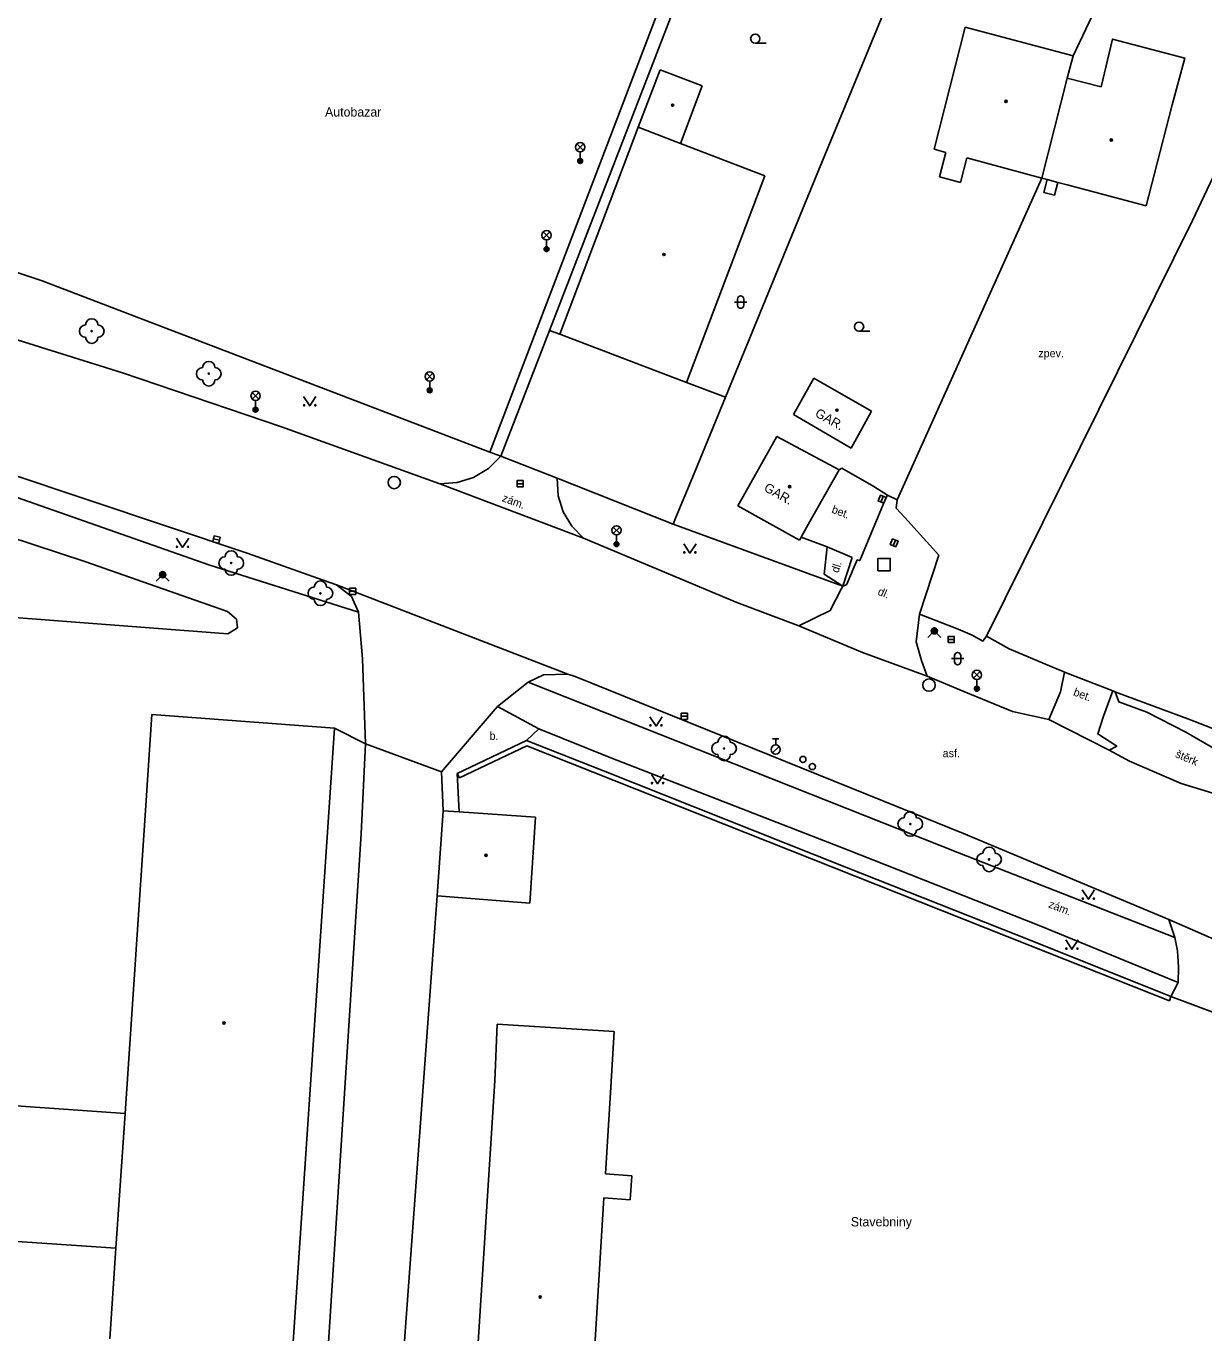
# Model space of a CAD drawing. Extents: x -598233 to -596890, y -1157848 to -1156431.
# Drawn here: x -597364.6 to -597268.9, y -1157742 to -1157635.8 of the extents above; entities that cross this region are included whole.
import ezdxf

# ---------------------------------------------------------------- set-up
doc = ezdxf.new("R2010")
doc.units = 0
for name, color, linetype in [('Level 10', 7, 'Continuous'), ('Level 11', 7, 'Continuous'), ('Level 22', 7, 'Continuous'), ('Level 26', 7, 'Continuous'), ('Level 27', 7, 'Continuous'), ('Level 28', 7, 'Continuous'), ('Level 31', 7, 'Continuous'), ('Level 33', 7, 'Continuous'), ('Level 36', 7, 'Continuous'), ('Level 39', 7, 'Continuous'), ('Level 40', 7, 'Continuous'), ('Level 41', 7, 'Continuous'), ('Level 42', 7, 'Continuous'), ('Level 5', 7, 'Continuous'), ('Level 51', 7, 'Continuous'), ('Level 7', 7, 'Continuous'), ('Level 8', 7, 'Continuous')]:
    doc.layers.add(name, color=color, linetype=linetype)

msp = doc.modelspace()

# ---------------------------------------------------------------- linework, layer by layer
at = {"layer": 'Level 10'}
for points in [[(-597382.9699, -1157656.14), (-597381.3, -1157656.62), (-597376.66, -1157657.97), (-597369.85, -1157659.94), (-597364.81, -1157661.47), (-597356.76, -1157664), (-597343.86, -1157668.37), (-597331.01, -1157673)], [(-597339.38, -1157681.22), (-597340.4696, -1157680.8289), (-597346.65, -1157678.64), (-597366.125, -1157672.11)], [(-597331.01, -1157673), (-597319.33, -1157677.42)], [(-597319.33, -1157677.42), (-597306.88, -1157682.64)], [(-597337.61, -1157683.43), (-597337.27, -1157687.21)], [(-597306.88, -1157682.64), (-597301.84, -1157684.53)], [(-597296.68, -1157686.72), (-597301.84, -1157684.53)], [(-597337.27, -1157687.21), (-597337.03, -1157694.12)], [(-597291.41, -1157688.64), (-597296.68, -1157686.72)], [(-597323.81, -1157689.12), (-597322.59, -1157688.52), (-597320.6, -1157688.47)], [(-597295.02, -1157698.76), (-597320.01, -1157688.6599), (-597320.6, -1157688.47)], [(-597288.44, -1157689.88), (-597291.41, -1157688.64)], [(-597326.32, -1157691.1), (-597323.81, -1157689.12)], [(-597288.44, -1157689.88), (-597284.49, -1157691.5)], [(-597330.87, -1157696.39), (-597326.5, -1157691.31), (-597326.32, -1157691.1)], [(-597281.53, -1157692.16), (-597284.49, -1157691.5)], [(-597276.64, -1157694.64), (-597281.53, -1157692.16)], [(-597275, -1157695.53), (-597276.64, -1157694.64)], [(-597270.8, -1157697.34), (-597275, -1157695.53)], [(-597266.62, -1157698.61), (-597270.8, -1157697.34)], [(-597295.02, -1157698.76), (-597288.48, -1157701.4099), (-597271.78, -1157708.38)], [(-597271.78, -1157708.38), (-597271.31, -1157709.84)], [(-597271.31, -1157709.84), (-597271.1, -1157710.94), (-597271, -1157712.26), (-597271.03, -1157713.5)], [(-597271.03, -1157713.5), (-597271.63, -1157714.64)]]:
    msp.add_lwpolyline(points, dxfattribs=at)
at = {"layer": 'Level 11'}
for points in [[(-597279.56, -1157638.27), (-597275.18, -1157629)], [(-597271.53, -1157642.24), (-597270.49, -1157638.44), (-597276.36, -1157636.89), (-597277.28, -1157640.77)], [(-597281.95, -1157649.36), (-597281.67, -1157648.3)], [(-597281.08, -1157649.58), (-597281.95, -1157649.36)], [(-597280.8, -1157648.53), (-597281.08, -1157649.58)], [(-597321.26, -1157660.87), (-597322.09, -1157660.56)], [(-597310.96, -1157664.78), (-597307.81, -1157665.97)], [(-597326.04, -1157670.77), (-597327.04, -1157671.76), (-597328.25, -1157672.49), (-597329.6, -1157672.9099), (-597331.01, -1157673)], [(-597319.33, -1157677.42), (-597320.28, -1157676.45), (-597320.9699, -1157675.29), (-597321.38, -1157673.99), (-597321.47, -1157672.56)], [(-597368.98, -1157672.85), (-597349.77, -1157679.58), (-597337.61, -1157683.43), (-597338.18, -1157682.16), (-597339.38, -1157681.22)], [(-597297.1, -1157679.17), (-597296.9, -1157679.25), (-597294.77, -1157674.17), (-597294.64, -1157673.94)], [(-597297.52, -1157679), (-597299.54, -1157678.14)], [(-597298.28, -1157681.32), (-597297.52, -1157679)], [(-597297.98, -1157681.22), (-597297.1, -1157679.17)], [(-597320.6, -1157688.47), (-597339.38, -1157681.22)], [(-597301.84, -1157684.53), (-597299.29, -1157683.3), (-597298.41, -1157681.56), (-597298.28, -1157681.32)], [(-597298.28, -1157681.32), (-597297.98, -1157681.22)], [(-597291.41, -1157688.64), (-597291.89, -1157687.36), (-597292.3, -1157685.84), (-597292.04, -1157683.6)], [(-597280.26, -1157688.3), (-597280.58, -1157689.89), (-597281.53, -1157692.16)], [(-597323.81, -1157689.12), (-597288.78, -1157702.99), (-597271.31, -1157709.84)], [(-597276.34, -1157689.83), (-597277.11, -1157691.88), (-597277.57, -1157693.32), (-597276.02, -1157694.31), (-597276.64, -1157694.64)], [(-597264.32, -1157694.38), (-597265.14, -1157694.86), (-597265.95, -1157695.13), (-597267.33, -1157694.96), (-597270.4, -1157693.19), (-597273.59, -1157691.54), (-597275.85, -1157690.72), (-597276.15, -1157689.91)], [(-597322.97, -1157692.91), (-597326.32, -1157691.1)], [(-597323.95, -1157693.84), (-597322.97, -1157692.91), (-597317.11, -1157695.26)], [(-597297.9, -1157702.72), (-597317.11, -1157695.26)], [(-597329.58, -1157696.52), (-597329.43, -1157699.65)], [(-597297.9, -1157702.72), (-597282.31, -1157708.88), (-597271.03, -1157713.5)], [(-597271.78, -1157708.38), (-597261.78, -1157712.78)], [(-597356.56, -1157724.13), (-597386.18, -1157722.07), (-597386.94, -1157733.07), (-597357.3, -1157735.09)]]:
    msp.add_lwpolyline(points, dxfattribs=at)
at = {"layer": 'Level 22'}
for centre in [(-597359.27, -1157660.61), (-597349.76, -1157664.07), (-597347.94, -1157679.44), (-597340.7, -1157681.9), (-597307.91, -1157694.5), (-597292.79, -1157700.63), (-597286.39, -1157703.51)]:
    msp.add_circle(centre, 0.05, dxfattribs=at)
for centre, start, end in [((-597359.27, -1157660.11), 0, 180), ((-597359.77, -1157660.61), 90, 270), ((-597359.27, -1157661.11), 180, 0), ((-597358.77, -1157660.61), 270, 90), ((-597349.76, -1157663.57), 0, 180), ((-597350.26, -1157664.07), 90, 270), ((-597349.26, -1157664.07), 270, 90), ((-597349.76, -1157664.57), 180, 0), ((-597348.44, -1157679.44), 90, 270), ((-597347.94, -1157678.94), 0, 180), ((-597347.44, -1157679.44), 270, 90), ((-597347.94, -1157679.94), 180, 0), ((-597340.7, -1157681.4), 0, 180), ((-597341.2, -1157681.9), 90, 270), ((-597340.2, -1157681.9), 270, 90), ((-597340.7, -1157682.4), 180, 0), ((-597308.41, -1157694.5), 90, 270), ((-597307.91, -1157694), 0, 180), ((-597307.41, -1157694.5), 270, 90), ((-597307.91, -1157695), 180, 0), ((-597293.29, -1157700.63), 90, 270), ((-597292.79, -1157700.13), 0, 180), ((-597292.29, -1157700.63), 270, 90), ((-597292.79, -1157701.13), 180, 0), ((-597286.39, -1157703.01), 0, 180), ((-597286.89, -1157703.51), 90, 270), ((-597285.89, -1157703.51), 270, 90), ((-597286.39, -1157704.01), 180, 0)]:
    msp.add_arc(centre, 0.5, start, end, dxfattribs=at)
at = {"layer": 'Level 26'}
msp.add_lwpolyline([(-597295.42, -1157680.07), (-597294.42, -1157680.07), (-597294.42, -1157679.07), (-597295.42, -1157679.07)], close=True, dxfattribs=at)
at = {"layer": 'Level 27'}
for p, q in [((-597324.72, -1157673), (-597324.22, -1157673)), ((-597295.1767, -1157674.4906), (-597294.9833, -1157674.0294)), ((-597349.3832, -1157677.4821), (-597348.8968, -1157677.5979)), ((-597294.1867, -1157678.0406), (-597293.9933, -1157677.5794)), ((-597338.32, -1157681.74), (-597337.82, -1157681.74)), ((-597289.72, -1157685.65), (-597289.22, -1157685.65)), ((-597311.39, -1157691.89), (-597310.89, -1157691.89))]:
    msp.add_line(p, q, dxfattribs=at)
for points in [[(-597324.72, -1157673.25), (-597324.22, -1157673.25), (-597324.22, -1157672.75), (-597324.72, -1157672.75)], [(-597294.9461, -1157674.5872), (-597294.7528, -1157674.1261), (-597295.2139, -1157673.9328), (-597295.4072, -1157674.3939)], [(-597349.4411, -1157677.7253), (-597348.9547, -1157677.8411), (-597348.8389, -1157677.3547), (-597349.3253, -1157677.2389)], [(-597293.9561, -1157678.1372), (-597293.7628, -1157677.6761), (-597294.2239, -1157677.4828), (-597294.4172, -1157677.9439)], [(-597338.32, -1157681.99), (-597337.82, -1157681.99), (-597337.82, -1157681.49), (-597338.32, -1157681.49)], [(-597289.72, -1157685.9), (-597289.22, -1157685.9), (-597289.22, -1157685.4), (-597289.72, -1157685.4)], [(-597311.39, -1157692.14), (-597310.89, -1157692.14), (-597310.89, -1157691.64), (-597311.39, -1157691.64)]]:
    msp.add_lwpolyline(points, close=True, dxfattribs=at)
for centre in [(-597334.7, -1157672.9099), (-597291.27, -1157689.35)]:
    msp.add_circle(centre, 0.5, dxfattribs=at)
at = {"layer": 'Level 28'}
for p, q in [((-597303.9699, -1157693.715), (-597303.4699, -1157693.715)), ((-597303.7199, -1157694.215), (-597303.7199, -1157693.715)), ((-597303.9779, -1157694.862), (-597303.4479, -1157694.332))]:
    msp.add_line(p, q, dxfattribs=at)
for centre, radius in [((-597303.7199, -1157694.59), 0.375), ((-597301.51, -1157695.39), 0.25), ((-597300.74, -1157695.9699), 0.25)]:
    msp.add_circle(centre, radius, dxfattribs=at)
at = {"layer": 'Level 31'}
for points in [[(-597354.04, -1157680.92), (-597353.51, -1157680.39), (-597352.98, -1157680.92)], [(-597291.37, -1157685.48), (-597290.84, -1157684.95), (-597290.31, -1157685.48)]]:
    msp.add_lwpolyline(points, dxfattribs=at)
for centre, radius in [((-597353.51, -1157680.39), 0.25), ((-597353.51, -1157680.39), 0.18), ((-597353.51, -1157680.39), 0.11), ((-597290.84, -1157684.95), 0.25), ((-597290.84, -1157684.95), 0.18), ((-597290.84, -1157684.95), 0.11)]:
    msp.add_circle(centre, radius, dxfattribs=at)
at = {"layer": 'Level 33'}
for p, q in [((-597319.865, -1157645.94), (-597319.335, -1157645.41)), ((-597319.865, -1157645.41), (-597319.335, -1157645.94)), ((-597319.6, -1157646.05), (-597319.6, -1157646.8)), ((-597322.595, -1157653.09), (-597322.065, -1157652.56)), ((-597322.595, -1157652.56), (-597322.065, -1157653.09)), ((-597322.33, -1157653.2), (-597322.33, -1157653.95)), ((-597332.085, -1157664.56), (-597331.555, -1157664.03)), ((-597332.085, -1157664.03), (-597331.555, -1157664.56)), ((-597331.82, -1157664.67), (-597331.82, -1157665.42)), ((-597346.225, -1157666.13), (-597345.695, -1157665.6)), ((-597346.225, -1157665.6), (-597345.695, -1157666.13)), ((-597345.96, -1157666.24), (-597345.96, -1157666.99)), ((-597316.915, -1157677.0499), (-597316.385, -1157676.5199)), ((-597316.915, -1157676.5199), (-597316.385, -1157677.0499)), ((-597316.65, -1157677.1599), (-597316.65, -1157677.9099)), ((-597287.645, -1157688.79), (-597287.115, -1157688.26)), ((-597287.645, -1157688.26), (-597287.115, -1157688.79)), ((-597287.38, -1157688.9), (-597287.38, -1157689.65))]:
    msp.add_line(p, q, dxfattribs=at)
for centre, radius in [((-597319.6, -1157645.675), 0.375), ((-597319.6, -1157646.8), 0.2), ((-597319.6, -1157646.8), 0.1445), ((-597319.6, -1157646.8), 0.0876), ((-597322.33, -1157652.825), 0.375), ((-597322.33, -1157653.95), 0.2), ((-597322.33, -1157653.95), 0.1445), ((-597322.33, -1157653.95), 0.0876), ((-597331.82, -1157664.295), 0.375), ((-597331.82, -1157665.42), 0.2), ((-597331.82, -1157665.42), 0.1445), ((-597331.82, -1157665.42), 0.0876), ((-597345.96, -1157665.865), 0.375), ((-597345.96, -1157666.99), 0.2), ((-597345.96, -1157666.99), 0.1445), ((-597345.96, -1157666.99), 0.0876), ((-597316.65, -1157676.7849), 0.375), ((-597316.65, -1157677.9099), 0.2), ((-597316.65, -1157677.9099), 0.1445), ((-597316.65, -1157677.9099), 0.0876), ((-597287.38, -1157688.525), 0.375), ((-597287.38, -1157689.65), 0.2), ((-597287.38, -1157689.65), 0.1445), ((-597287.38, -1157689.65), 0.0876)]:
    msp.add_circle(centre, radius, dxfattribs=at)
at = {"layer": 'Level 36'}
for p, q in [((-597305.38, -1157637.235), (-597304.505, -1157637.235)), ((-597307.066, -1157658.256), (-597306.066, -1157658.256)), ((-597306.816, -1157658.006), (-597306.816, -1157658.506)), ((-597306.316, -1157658.006), (-597306.316, -1157658.506)), ((-597296.95, -1157660.625), (-597296.075, -1157660.625)), ((-597289.446, -1157687.206), (-597288.446, -1157687.206)), ((-597289.196, -1157686.956), (-597289.196, -1157687.456)), ((-597288.696, -1157686.956), (-597288.696, -1157687.456))]:
    msp.add_line(p, q, dxfattribs=at)
for points in [[(-597342.06, -1157665.93), (-597341.56, -1157666.68), (-597341.06, -1157665.93)], [(-597352.39, -1157677.43), (-597351.89, -1157678.18), (-597351.39, -1157677.43)], [(-597311.19, -1157677.88), (-597310.69, -1157678.63), (-597310.19, -1157677.88)], [(-597313.94, -1157691.93), (-597313.44, -1157692.68), (-597312.94, -1157691.93)], [(-597313.81, -1157696.61), (-597313.31, -1157697.36), (-597312.81, -1157696.61)], [(-597278.83, -1157705.99), (-597278.33, -1157706.74), (-597277.83, -1157705.99)], [(-597280.1599, -1157710.05), (-597279.6599, -1157710.8), (-597279.1599, -1157710.05)]]:
    msp.add_lwpolyline(points, dxfattribs=at)
for centre, radius in [((-597305.3801, -1157636.8599), 0.375), ((-597296.9501, -1157660.2499), 0.375), ((-597342.0102, -1157666.6298), 0.05), ((-597341.1108, -1157666.6298), 0.05), ((-597352.3402, -1157678.1298), 0.05), ((-597351.4408, -1157678.1298), 0.05), ((-597311.1402, -1157678.5798), 0.05), ((-597310.2408, -1157678.5798), 0.05), ((-597313.8902, -1157692.6298), 0.05), ((-597312.9908, -1157692.6298), 0.05), ((-597313.7602, -1157697.3098), 0.05), ((-597312.8608, -1157697.3098), 0.05), ((-597278.7802, -1157706.6898), 0.05), ((-597277.8808, -1157706.6898), 0.05), ((-597280.1101, -1157710.7498), 0.05), ((-597279.2107, -1157710.7498), 0.05)]:
    msp.add_circle(centre, radius, dxfattribs=at)
for centre, start, end in [((-597306.5657, -1157658.0063), 0, 180), ((-597306.5657, -1157658.5063), 180, 0), ((-597288.9457, -1157686.9563), 0, 180), ((-597288.9457, -1157687.4563), 180, 0)]:
    msp.add_arc(centre, 0.25, start, end, dxfattribs=at)
at = {"layer": 'Level 39'}
for centre, radius in [((-597285.01, -1157641.96), 0.09), ((-597285.01, -1157641.96), 0.0398), ((-597312.09, -1157642.26), 0.09), ((-597312.09, -1157642.26), 0.0398), ((-597276.4699, -1157645.09), 0.09), ((-597276.4699, -1157645.09), 0.0398), ((-597312.8, -1157654.39), 0.09), ((-597312.8, -1157654.39), 0.0398), ((-597298.75, -1157667.03), 0.09), ((-597298.75, -1157667.03), 0.0398), ((-597302.59, -1157673.24), 0.09), ((-597302.59, -1157673.24), 0.0398), ((-597327.25, -1157703.18), 0.09), ((-597327.25, -1157703.18), 0.0398), ((-597348.53, -1157716.8), 0.09), ((-597348.53, -1157716.8), 0.0398), ((-597322.85, -1157739.05), 0.09), ((-597322.85, -1157739.05), 0.0398)]:
    msp.add_circle(centre, radius, dxfattribs=at)
at = {"layer": 'Level 5'}
for points in [[(-597290.84, -1157645.84), (-597288.32, -1157635.92)], [(-597288.32, -1157635.92), (-597279.56, -1157638.27)], [(-597279.56, -1157638.27), (-597280.04, -1157640.07)], [(-597314.89, -1157644.06), (-597313.1, -1157639.39)], [(-597313.1, -1157639.39), (-597309.68, -1157640.7)], [(-597309.68, -1157640.7), (-597311.46, -1157645.38)], [(-597280.04, -1157640.07), (-597282.11, -1157648.18)], [(-597280.04, -1157640.07), (-597277.28, -1157640.77)], [(-597271.53, -1157642.24), (-597272.5, -1157646.02)], [(-597321.26, -1157660.87), (-597314.89, -1157644.06)], [(-597314.89, -1157644.06), (-597311.46, -1157645.38)], [(-597311.46, -1157645.38), (-597304.59, -1157647.99)], [(-597289.89, -1157646.1), (-597290.84, -1157645.84)], [(-597290.42, -1157648.08), (-597289.89, -1157646.1)], [(-597272.5, -1157646.02), (-597273.64, -1157650.45)], [(-597288.19, -1157646.55), (-597288.7199, -1157648.54)], [(-597282.11, -1157648.18), (-597288.19, -1157646.55)], [(-597304.59, -1157647.99), (-597310.96, -1157664.78)], [(-597288.7199, -1157648.54), (-597290.42, -1157648.08)], [(-597281.67, -1157648.3), (-597282.11, -1157648.18)], [(-597280.8, -1157648.53), (-597281.67, -1157648.3)], [(-597280.06, -1157648.7199), (-597280.8, -1157648.53)], [(-597273.64, -1157650.45), (-597280.06, -1157648.7199)], [(-597310.96, -1157664.78), (-597321.26, -1157660.87)], [(-597302.27, -1157667.37), (-597300.63, -1157664.44)], [(-597300.63, -1157664.44), (-597295.93, -1157667.11)], [(-597297.59, -1157670.11), (-597302.27, -1157667.37)], [(-597295.93, -1157667.11), (-597297.59, -1157670.11)], [(-597306.37, -1157674.04), (-597303.64, -1157669.17)], [(-597303.64, -1157669.17), (-597298.57, -1157671.87)], [(-597298.57, -1157671.87), (-597300.94, -1157676.08)], [(-597306.8, -1157674.81), (-597306.37, -1157674.04)], [(-597301.79, -1157677.58), (-597306.8, -1157674.81)], [(-597300.94, -1157676.08), (-597301.66, -1157677.35), (-597301.79, -1157677.58)], [(-597354.88, -1157699.13), (-597354.38, -1157691.74)], [(-597354.38, -1157691.74), (-597339.56, -1157692.85)], [(-597342.9699, -1157743.49), (-597339.56, -1157692.85)], [(-597354.88, -1157699.13), (-597356.56, -1157724.13), (-597357.3, -1157735.09), (-597357.79, -1157742.43)], [(-597331.2, -1157706.4699), (-597330.7199, -1157699.56)], [(-597330.7199, -1157699.56), (-597329.43, -1157699.65), (-597323.23, -1157700.07)], [(-597323.23, -1157700.07), (-597323.68, -1157707.06)], [(-597323.68, -1157707.06), (-597331.2, -1157706.4699)], [(-597326.52, -1157721.49), (-597326.34, -1157716.9)], [(-597326.34, -1157716.9), (-597316.84, -1157717.48)], [(-597316.84, -1157717.48), (-597317.12, -1157722)], [(-597328.85, -1157758), (-597326.52, -1157721.49)], [(-597317.55, -1157729.04), (-597317.12, -1157722)], [(-597315.4, -1157729.2), (-597317.55, -1157729.04)], [(-597315.54, -1157731.14), (-597315.4, -1157729.2)], [(-597317.67, -1157730.98), (-597319.36, -1157758.55)], [(-597317.67, -1157730.98), (-597315.54, -1157731.14)]]:
    msp.add_lwpolyline(points, dxfattribs=at)
at = {"layer": 'Level 51'}
for points in [[(-597370.39, -1157675.84), (-597359.84, -1157679.31)], [(-597359.84, -1157679.31), (-597348.25, -1157683.38)], [(-597348.25, -1157683.38), (-597347.52, -1157684.01)], [(-597367.67, -1157683.71), (-597348.2199, -1157685.18)], [(-597347.52, -1157684.01), (-597347.44, -1157684.71)], [(-597348.2199, -1157685.18), (-597347.44, -1157684.71)], [(-597337.38, -1157701.44), (-597337.03, -1157694.12)], [(-597330.87, -1157696.39), (-597330.7199, -1157699.56)], [(-597340.37, -1157747.81), (-597337.38, -1157701.44)], [(-597333.99, -1157744.43), (-597331.2, -1157706.4699)]]:
    msp.add_lwpolyline(points, dxfattribs=at)
at = {"layer": 'Level 7'}
for points in [[(-597326.04, -1157670.77), (-597322.09, -1157660.56), (-597304.52, -1157615.14)], [(-597306.09, -1157615.82), (-597326.93, -1157670.43)], [(-597312.06, -1157676.28), (-597311.87, -1157675.8), (-597310.49, -1157672.49), (-597307.81, -1157665.97), (-597300.24, -1157647.57), (-597292.3, -1157628.34)], [(-597262.75, -1157636.58), (-597269.87, -1157651.62), (-597286.6, -1157685.39)], [(-597282.11, -1157648.18), (-597284.23, -1157652.9)], [(-597363.3, -1157656.54), (-597375.03, -1157652.6), (-597381.15, -1157650.54)], [(-597284.23, -1157652.9), (-597293.86, -1157674.3)], [(-597326.93, -1157670.43), (-597363.3, -1157656.54)], [(-597326.04, -1157670.77), (-597326.93, -1157670.43)], [(-597298.57, -1157671.87), (-597298.34, -1157671.75)], [(-597321.47, -1157672.56), (-597312.06, -1157676.28)], [(-597295.76, -1157673.22), (-597294.64, -1157673.94)], [(-597293.86, -1157674.3), (-597293.94, -1157675)], [(-597312.06, -1157676.28), (-597298.28, -1157681.32)], [(-597301.66, -1157677.35), (-597299.54, -1157678.14), (-597299.79, -1157680.36)], [(-597290.48, -1157678.8), (-597292.04, -1157683.6)], [(-597298.28, -1157681.32), (-597299.79, -1157680.36)], [(-597292.04, -1157683.6), (-597288.9, -1157684.82)], [(-597288.9, -1157684.82), (-597287.76, -1157685.31)], [(-597287.76, -1157685.31), (-597286.89, -1157685.78), (-597286.6, -1157685.39), (-597284.75, -1157686.42), (-597280.78, -1157688.09)], [(-597339.56, -1157692.85), (-597337.03, -1157694.12)], [(-597270.26, -1157692.09), (-597264.89, -1157694.18)], [(-597329.58, -1157696.52), (-597323.95, -1157693.84), (-597317.7, -1157696.32), (-597297.97, -1157704.17), (-597282.93, -1157710.13), (-597271.63, -1157714.64)], [(-597329.4, -1157696.89), (-597323.93, -1157694.28), (-597283.08, -1157710.5), (-597271.75, -1157714.98)], [(-597329.58, -1157696.52), (-597329.4, -1157696.89)], [(-597271.75, -1157714.98), (-597271.63, -1157714.64)]]:
    msp.add_lwpolyline(points, dxfattribs=at)
at = {"layer": 'Level 8'}
for points in [[(-597326.04, -1157670.77), (-597321.47, -1157672.56)], [(-597298.34, -1157671.75), (-597295.76, -1157673.22)], [(-597293.86, -1157674.3), (-597294.64, -1157673.94)], [(-597293.94, -1157675), (-597293.23, -1157675.74), (-597290.48, -1157678.8)], [(-597275.89, -1157690.01), (-597276.15, -1157689.91), (-597276.34, -1157689.83), (-597280.26, -1157688.3), (-597280.42, -1157688.23), (-597280.78, -1157688.09)], [(-597275.89, -1157690.01), (-597270.26, -1157692.09)], [(-597330.87, -1157696.39), (-597337.03, -1157694.12)], [(-597265.96, -1157716.76), (-597271.63, -1157714.64)]]:
    msp.add_lwpolyline(points, dxfattribs=at)

# ---------------------------------------------------------------- texts
at = {"layer": 'Level 40'}
for s, p in [('zpev.', (-597282.39, -1157662.73)), ('b.', (-597326.96, -1157693.8)), ('asf.', (-597290.16, -1157695.21))]:
    msp.add_text(s, height=0.65, dxfattribs=at).set_placement(p)
for s, rotation, p in [('zám.', 339.837396, (-597325.99, -1157674.41)), ('bet.', 339.502659, (-597299.23, -1157675.34)), ('dl.', 71.861918, (-597298.63, -1157680.29)), ('dl.', 337.002729, (-597295.49, -1157681.99)), ('bet.', 339.502659, (-597279.6, -1157690.17)), ('štěrk', 336.686259, (-597271.32, -1157695.18)), ('zám.', 338.589817, (-597281.62, -1157707.39))]:
    msp.add_text(s, height=0.65, rotation=rotation, dxfattribs=at).set_placement(p)
at = {"layer": 'Level 41'}
for p in [(-597300.59, -1157667.49), (-597304.74, -1157673.54)]:
    msp.add_text('GAR.', height=0.75, rotation=330.655782, dxfattribs=at).set_placement(p)
at = {"layer": 'Level 42'}
for s, p in [('Autobazar', (-597340.32, -1157643.19)), ('Stavebniny', (-597297.62, -1157733.31))]:
    msp.add_text(s, height=0.75, dxfattribs=at).set_placement(p)

doc.saveas('drawing.dxf')
